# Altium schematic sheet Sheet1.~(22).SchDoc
size A3; SheetNumber: 1; SheetTotal: 2
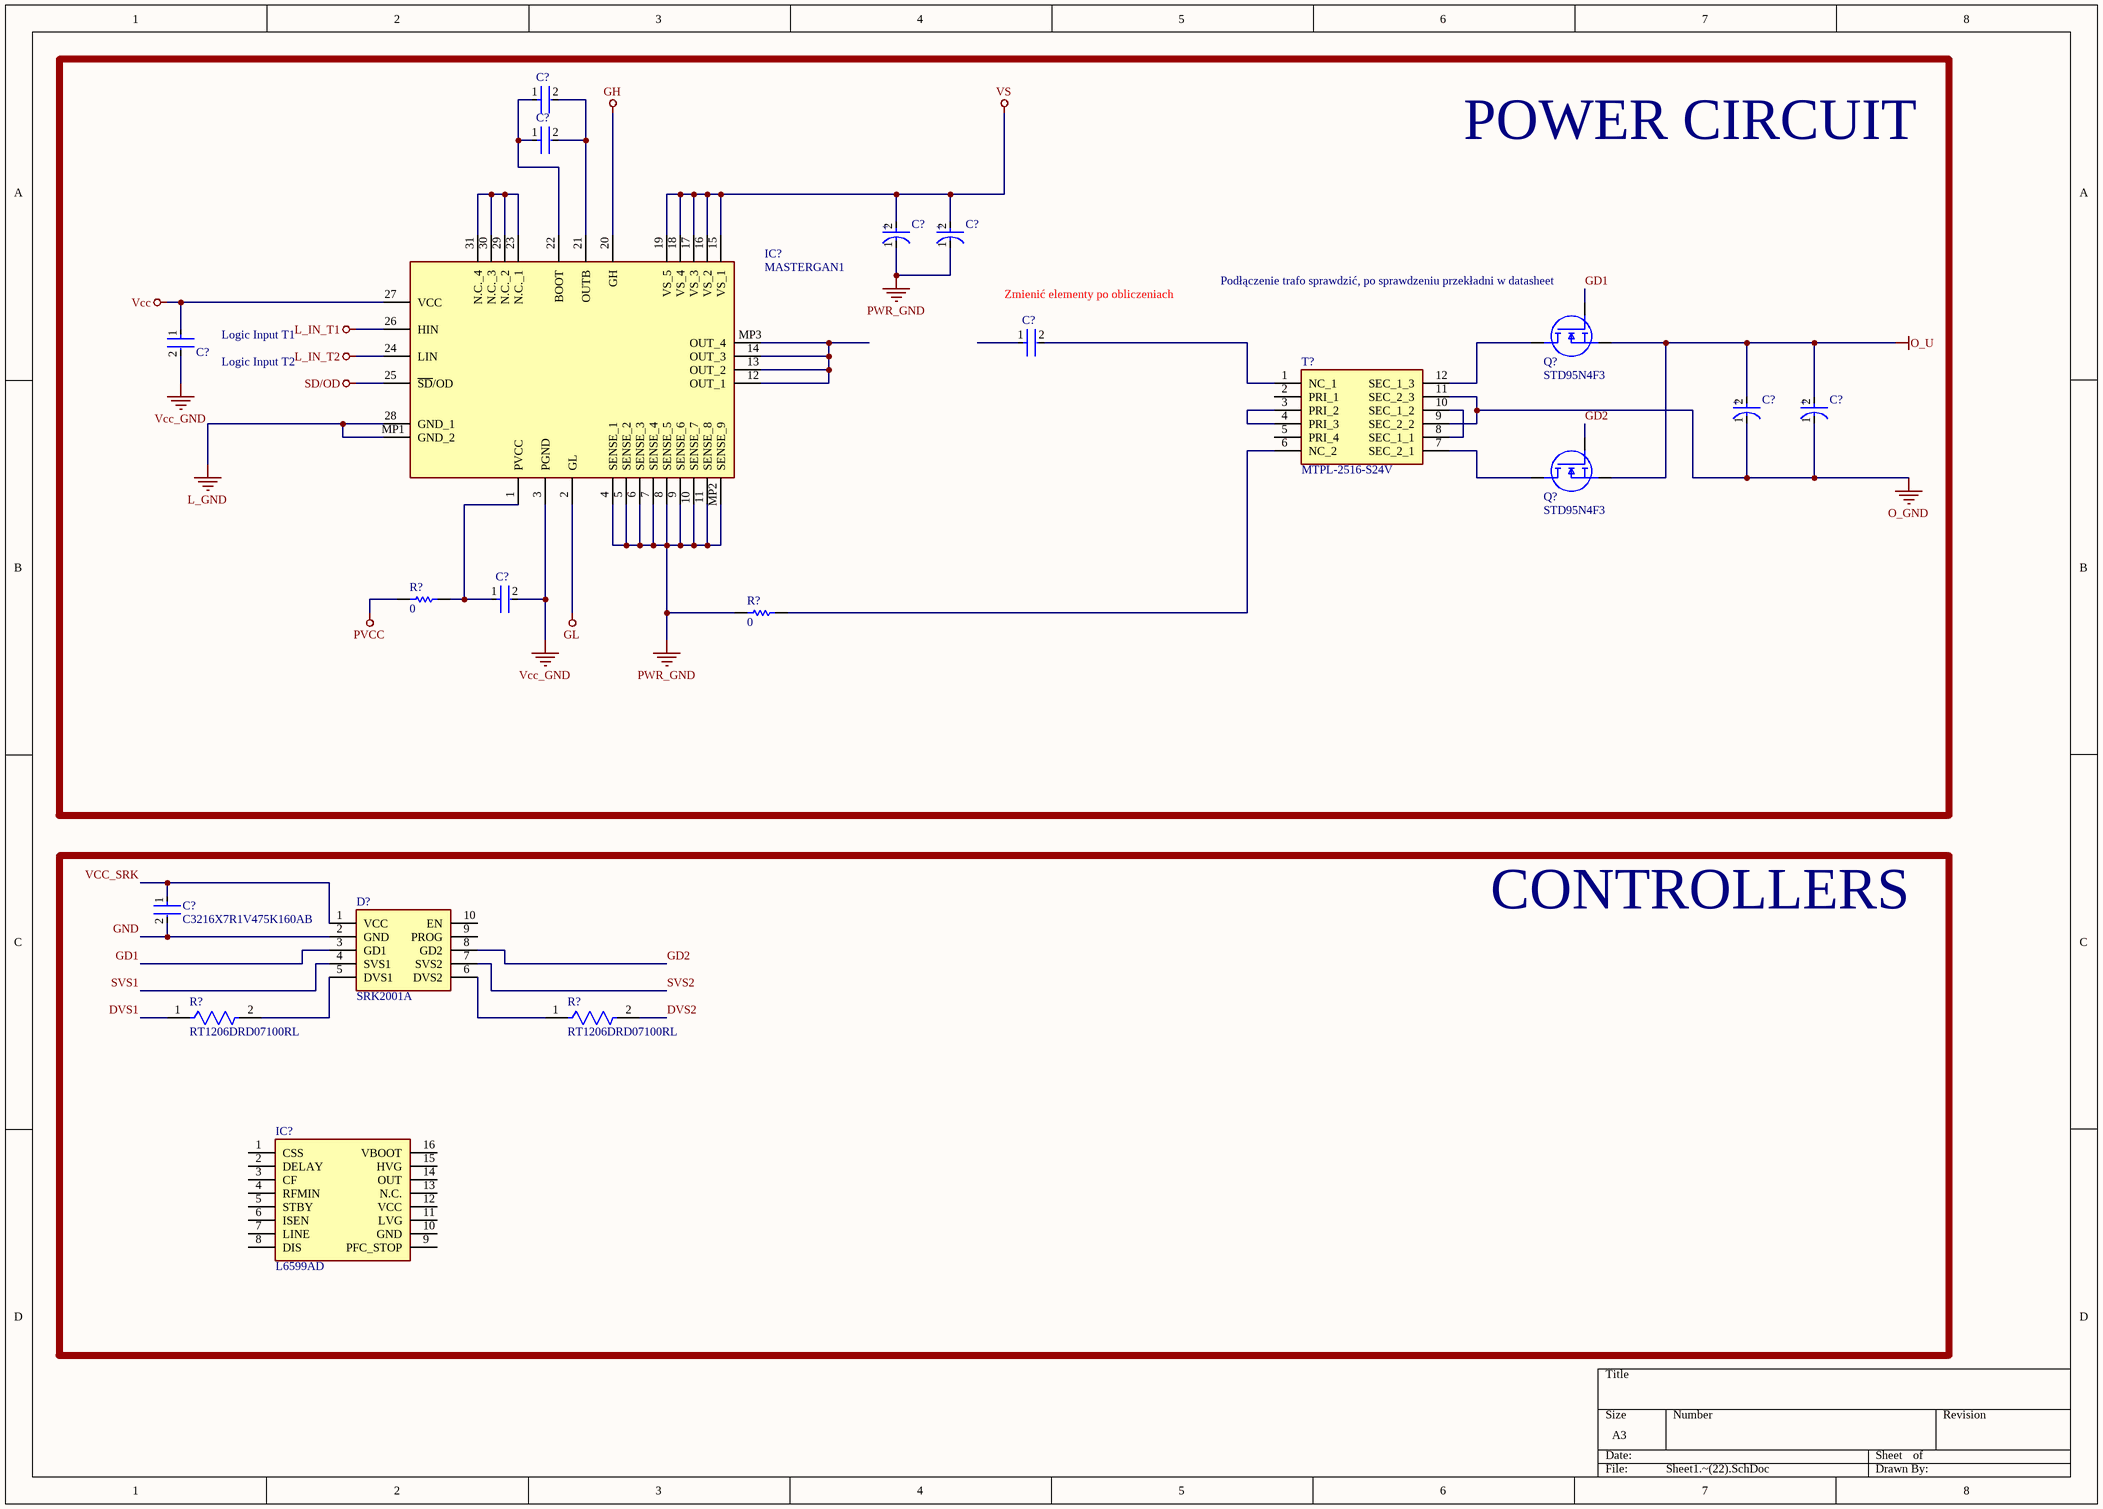
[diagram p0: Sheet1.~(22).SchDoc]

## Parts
(Parts that share a designator on the sheet are numbered #1, #2 ... from top to bottom, then left to right.)
C?#1  C3216X7R1V475K160AB  [FP-C3216-160-0_2-IPC_C]  (value not drawn)
C?#2  C3216X7R1V475K160AB  [FP-C3216-160-0_2-IPC_C]  (value not drawn)
C?#3  450BXW100MEFR18X30  [FP-BXW18X30-MFG]  (value not drawn)
C?#4  450BXW100MEFR18X30  [FP-BXW18X30-MFG]  (value not drawn)
C?#5  C3216X7R1V475K160AB  [FP-C3216-160-0_2-IPC_C]  (value not drawn)
C?#6  C3216X7R1V475K160AB  [FP-C3216-160-0_2-IPC_C]  (value not drawn)
C?#7  450BXW100MEFR18X30  [FP-BXW18X30-MFG]  (value not drawn)
C?#8  450BXW100MEFR18X30  [FP-BXW18X30-MFG]  (value not drawn)
C?#9  C3216X7R1V475K160AB  [FP-C3216-160-0_2-IPC_C]  (value not drawn)
C?#10  C3216X7R1V475K160AB  [FP-C3216-160-0_2-IPC_C]
D?  SRK2001A  [SOIC127P600X175-8N]
IC?#1  MASTERGAN1  [MASTERGAN1]
IC?#2  L6599AD  [SOIC127P600X175-16N]
Q?#1  STD95N4F3  [STD95N4F3]
Q?#2  STD95N4F3  [STD95N4F3]
R?#1  value 0  (hidden comment: Resistor)
R?#2  value 0  (hidden comment: Resistor)
R?#3  RT1206DRD07100RL  [FP-RT1206-MFG]
R?#4  RT1206DRD07100RL  [FP-RT1206-MFG]
T?  MTPL-2516-S24V  [MTPL2516S24V]

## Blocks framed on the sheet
POWER CIRCUIT: C?#1-C?#9 IC?#1 Q?#1 Q?#2 R?#1 R?#2 T?
CONTROLLERS: C?#10 D? IC?#2 R?#3 R?#4

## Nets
GH: IC?#1.20(GH)
GL: IC?#1.2(GL)
L_GND: IC?#1.28(GND_1) IC?#1.MP1(GND_2)
L_IN_T1: IC?#1.26(HIN)
L_IN_T2: IC?#1.24(LIN)
O_GND: C?#7.1(C) C?#8.1(C) T?.9(SEC_2_2) T?.11(SEC_2_3)
O_U: C?#7.2(A) C?#8.2(A) Q?#1.3(S) Q?#2.3(S)
PVCC: R?#1.1
PWR_GND: C?#3.1(C) C?#4.1(C) IC?#1.4(SENSE_1) IC?#1.5(SENSE_2) IC?#1.6(SENSE_3) IC?#1.7(SENSE_4) IC?#1.8(SENSE_5) IC?#1.9(SENSE_6) IC?#1.10(SENSE_7) IC?#1.11(SENSE_8) IC?#1.MP2(SENSE_9) R?#2.1
SD/OD: IC?#1.25(~{SD}/OD)
Vcc: C?#5.1 IC?#1.27(VCC)
Vcc_GND: C?#5.2 C?#9.2 IC?#1.3(PGND)
VS: C?#3.2(A) C?#4.2(A) IC?#1.15(VS_1) IC?#1.16(VS_2) IC?#1.17(VS_3) IC?#1.18(VS_4) IC?#1.19(VS_5)
DVS1: R?#3.1
DVS2: R?#4.2
GD1: D?.3(GD1) Q?#1.1(G)
GD2: D?.8(GD2) Q?#2.1(G)
GND: C?#10.2 D?.2(GND)
SVS1: D?.4(SVS1)
SVS2: D?.7(SVS2)
VCC_SRK: C?#10.1 D?.1(VCC)
NetC?#1_1: C?#1.1 C?#2.1 IC?#1.22(BOOT)
NetC?#1_2: C?#1.2 C?#2.2 IC?#1.21(OUTB)
NetC?#6_2: C?#6.2 T?.1(NC_1)
NetC?#9_1: C?#9.1 IC?#1.1(PVCC) R?#1.2
NetD?_5: D?.5(DVS1) R?#3.2
NetD?_6: D?.6(DVS2) R?#4.1
NetIC?#1_12: IC?#1.12(OUT_1) IC?#1.13(OUT_2) IC?#1.14(OUT_3) IC?#1.MP3(OUT_4)
NetIC?#1_23: IC?#1.23(N.C._1) IC?#1.29(N.C._2) IC?#1.30(N.C._3) IC?#1.31(N.C._4)
NetQ?#1_4: Q?#1.4(D) T?.12(SEC_1_3)
NetQ?#2_4: Q?#2.4(D) T?.7(SEC_2_1)
NetR?#2_2: R?#2.2 T?.6(NC_2)
NetT?_3: T?.3(PRI_2) T?.4(PRI_3)
NetT?_8: T?.8(SEC_1_1) T?.10(SEC_1_2)

Not connected (* = marked no-connect by the designer): C?#6 1; D? 9(PROG) 10(EN); IC?#2 1(CSS) 2(DELAY) 3(CF) 4(RFMIN) 5(STBY) 6(ISEN) 7(LINE) 8(DIS) 9(PFC_STOP) 10(GND) 11(LVG) 12(VCC) 13(N.C.) 14(OUT) 15(HVG) 16(VBOOT); T? 2(PRI_1) 5(PRI_4)

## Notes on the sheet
- (near C?#6) Zmienić elementy po obliczeniach
- (near Q?#1) Podłączenie trafo sprawdzić, po sprawdzeniu przekładni w datasheet
- (near C?#5) Logic Input T1
- (near C?#5) Logic Input T2

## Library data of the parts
C?#1 C?#2 C?#5 C?#6 C?#9 C?#10 = CMP-08246-003663-1: Multilayer Ceramic Capacitors 4.7uF ±10% 35V X7R SMD 1206
C?#3 C?#4 C?#7 C?#8 = CMP-35376-000021-1: CAP ALUM 100UF 20% 450V RADIAL; Polarity: Polar; Life (Hours): 12000Hour; Ripple Current: 750mA
D? = SRK2001A: Diode; Manufacturer_Name: STMicroelectronics
IC?#1 = MASTERGAN1: Integrated Circuit; Manufacturer_Name: STMicroelectronics
IC?#2 = L6599AD: Integrated Circuit; Manufacturer_Name: STMicroelectronics
Q?#1 Q?#2 = STD95N4F3: MOSFET (N-Channel); Manufacturer_Name: STMicroelectronics
R?#1 R?#2 = Resistor: SimulationGenericComponent: True
R?#3 R?#4 = CMP-03412-027315-1: RES 100 OHM 1/4W .5% SMD 1206; Manufacturer: Yageo; Voltage Rating: 200V; Resistance: 100Ω; Power Rating: 0.25W; Value: 100Ω; Temperature Coefficient: 25 ppm/°C; Tolerance: 0.0001
T? = MTPL-2516-S24V: Transformer; Manufacturer_Name: Vishay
